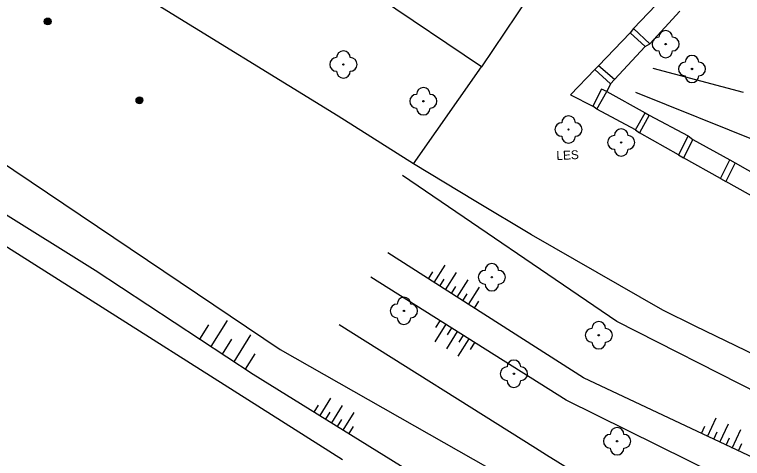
# Model space of a CAD drawing. Extents: x -539515 to -538098, y -1182060 to -1180157.
# Drawn here: x -538510.9 to -538457.6, y -1181768.2 to -1181735.7 of the extents above; entities that cross this region are included whole.
import ezdxf

# ---------------------------------------------------------------- set-up
doc = ezdxf.new("R2010")
doc.units = 0
for name, color, linetype in [('Vrstva 1', 7, 'Continuous'), ('Vrstva 13', 7, 'Continuous'), ('Vrstva 21', 7, 'Continuous'), ('Vrstva 22', 7, 'Continuous'), ('Vrstva 25', 7, 'Continuous'), ('Vrstva 27', 7, 'Continuous'), ('Vrstva 29', 7, 'Continuous'), ('Vrstva 40', 7, 'Continuous'), ('Vrstva 68', 7, 'Continuous'), ('Vrstva 88', 7, 'Continuous')]:
    doc.layers.add(name, color=color, linetype=linetype)

msp = doc.modelspace()

# ---------------------------------------------------------------- linework, layer by layer
at = {"layer": 'Vrstva 1'}
for p, q in [((-538476.685, -1181739.538), (-538490.817, -1181729.986)), ((-538471.65, -1181732.06), (-538476.685, -1181739.538))]:
    msp.add_line(p, q, dxfattribs=at)
at = {"layer": 'Vrstva 13'}
for p, q in [((-538465.54, -1181736.72), (-538465.78, -1181737.04)), ((-538465.78, -1181737.04), (-538464.69, -1181738.04)), ((-538464.33, -1181737.84), (-538465.54, -1181736.72)), ((-538464.69, -1181738.04), (-538464.33, -1181737.84)), ((-538466.92, -1181740.45), (-538468.11, -1181739.46)), ((-538464.13, -1181739.64), (-538457.51, -1181741.38)), ((-538467.23, -1181740.78), (-538466.92, -1181740.45)), ((-538468.22, -1181742.63), (-538467.48, -1181741.35)), ((-538465.39, -1181741.38), (-538456.26, -1181745.06)), ((-538468.22, -1181742.63), (-538468.52, -1181742.4)), ((-538465.397, -1181744.143), (-538464.68, -1181742.9)), ((-538464.68, -1181742.9), (-538464.38, -1181743.06)), ((-538464.38, -1181743.06), (-538465.1, -1181744.37)), ((-538465.397, -1181744.143), (-538465.1, -1181744.37)), ((-538461.54, -1181744.58), (-538462.235, -1181745.981)), ((-538461.54, -1181744.58), (-538461.2, -1181744.85)), ((-538461.2, -1181744.85), (-538461.865, -1181746.189)), ((-538462.235, -1181745.981), (-538461.865, -1181746.189)), ((-538459.161, -1181747.71), (-538458.47, -1181746.33)), ((-538458.09, -1181746.56), (-538458.77, -1181747.93)), ((-538458.47, -1181746.33), (-538458.09, -1181746.56)), ((-538459.161, -1181747.71), (-538458.77, -1181747.93))]:
    msp.add_line(p, q, dxfattribs=at)
for points in [[(-538468.11, -1181739.46), (-538468.37, -1181739.73), (-538467.23, -1181740.78)], [(-538467.48, -1181741.35), (-538467.89, -1181741.16), (-538468.52, -1181742.4)]]:
    msp.add_lwpolyline(points, dxfattribs=at)
at = {"layer": 'Vrstva 21'}
msp.add_line((-538481.67, -1181746.64), (-538476.685, -1181739.538), dxfattribs=at)
at = {"layer": 'Vrstva 22'}
for centre in [(-538463.18, -1181737.87), (-538486.8, -1181739.36), (-538461.25, -1181739.69), (-538480.94, -1181742.05), (-538470.3, -1181744.12), (-538466.44, -1181745.07), (-538475.92, -1181754.94), (-538482.36, -1181757.4), (-538468.08, -1181759.19), (-538474.3, -1181762), (-538466.74, -1181766.95)]:
    msp.add_circle(centre, 0.05, dxfattribs=at)
for centre, start, end in [((-538463.18, -1181737.37), 0, 180), ((-538463.68, -1181737.87), 90, 270), ((-538462.68, -1181737.87), 270, 90), ((-538486.8, -1181738.86), 0, 180), ((-538463.18, -1181738.37), 180, 0), ((-538461.25, -1181739.19), 0, 180), ((-538487.3, -1181739.36), 90, 270), ((-538486.3, -1181739.36), 270, 90), ((-538461.75, -1181739.69), 90, 270), ((-538460.75, -1181739.69), 270, 90), ((-538486.8, -1181739.86), 180, 0), ((-538461.25, -1181740.19), 180, 0), ((-538480.94, -1181741.55), 0, 180), ((-538481.44, -1181742.05), 90, 270), ((-538480.44, -1181742.05), 270, 90), ((-538480.94, -1181742.55), 180, 0), ((-538470.3, -1181743.62), 0, 180), ((-538470.8, -1181744.12), 90, 270), ((-538469.8, -1181744.12), 270, 90), ((-538466.94, -1181745.07), 90, 270), ((-538466.44, -1181744.57), 0, 180), ((-538465.94, -1181745.07), 270, 90), ((-538470.3, -1181744.62), 180, 0), ((-538466.44, -1181745.57), 180, 0), ((-538475.92, -1181754.44), 0, 180), ((-538476.42, -1181754.94), 90, 270), ((-538475.42, -1181754.94), 270, 90), ((-538475.92, -1181755.44), 180, 0), ((-538482.36, -1181756.9), 0, 180), ((-538482.86, -1181757.4), 90, 270), ((-538481.86, -1181757.4), 270, 90), ((-538482.36, -1181757.9), 180, 0), ((-538468.08, -1181758.69), 0, 180), ((-538468.58, -1181759.19), 90, 270), ((-538467.58, -1181759.19), 270, 90), ((-538468.08, -1181759.69), 180, 0), ((-538474.3, -1181761.5), 0, 180), ((-538474.8, -1181762), 90, 270), ((-538473.8, -1181762), 270, 90), ((-538474.3, -1181762.5), 180, 0), ((-538467.24, -1181766.95), 90, 270), ((-538466.74, -1181766.45), 0, 180), ((-538466.24, -1181766.95), 270, 90), ((-538466.74, -1181767.45), 180, 0)]:
    msp.add_arc(centre, 0.5, start, end, dxfattribs=at)
at = {"layer": 'Vrstva 25'}
for centre, radius in [((-538508.475, -1181736.21), 0.25), ((-538508.475, -1181736.21), 0.2), ((-538508.475, -1181736.21), 0.15), ((-538508.475, -1181736.21), 0.1), ((-538508.475, -1181736.21), 0.05), ((-538501.751, -1181741.979), 0.25), ((-538501.751, -1181741.979), 0.2), ((-538501.751, -1181741.979), 0.15), ((-538501.751, -1181741.979), 0.1), ((-538501.751, -1181741.979), 0.05)]:
    msp.add_circle(centre, radius, dxfattribs=at)
at = {"layer": 'Vrstva 27'}
for p, q in [((-538480.15, -1181755.325), (-538479.343, -1181754.06)), ((-538480.571, -1181755.055), (-538480.249, -1181754.55)), ((-538479.307, -1181755.863), (-538478.5, -1181754.598)), ((-538479.729, -1181755.594), (-538479.406, -1181755.088)), ((-538478.464, -1181756.401), (-538477.657, -1181755.137)), ((-538478.886, -1181756.132), (-538478.563, -1181755.626)), ((-538477.622, -1181756.939), (-538476.814, -1181755.675)), ((-538478.043, -1181756.67), (-538477.72, -1181756.164)), ((-538477.2, -1181757.208), (-538476.877, -1181756.702)), ((-538497.322, -1181759.469), (-538496.67, -1181758.423)), ((-538496.487, -1181760.019), (-538495.293, -1181758.104)), ((-538479.298, -1181758.386), (-538480.096, -1181759.656)), ((-538479.721, -1181758.12), (-538480.04, -1181758.628)), ((-538478.451, -1181758.918), (-538479.249, -1181760.188)), ((-538478.874, -1181758.652), (-538479.193, -1181759.16)), ((-538495.651, -1181760.57), (-538494.973, -1181759.481)), ((-538494.816, -1181761.12), (-538493.595, -1181759.162)), ((-538477.604, -1181759.45), (-538478.402, -1181760.72)), ((-538478.028, -1181759.184), (-538478.347, -1181759.692)), ((-538477.181, -1181759.716), (-538477.5, -1181760.224)), ((-538493.981, -1181761.67), (-538493.276, -1181760.539)), ((-538488.508, -1181765.073), (-538487.72, -1181763.797)), ((-538488.933, -1181764.81), (-538488.618, -1181764.3)), ((-538487.657, -1181765.599), (-538486.869, -1181764.322)), ((-538488.083, -1181765.336), (-538487.767, -1181764.825)), ((-538486.806, -1181766.124), (-538486.018, -1181764.848)), ((-538487.232, -1181765.861), (-538486.917, -1181765.351)), ((-538460.111, -1181766.591), (-538459.473, -1181765.234)), ((-538486.381, -1181766.387), (-538486.066, -1181765.876)), ((-538460.564, -1181766.378), (-538460.308, -1181765.835)), ((-538459.206, -1181767.017), (-538458.568, -1181765.66)), ((-538459.659, -1181766.804), (-538459.403, -1181766.261)), ((-538458.301, -1181767.443), (-538457.663, -1181766.085)), ((-538458.754, -1181767.23), (-538458.498, -1181766.687)), ((-538457.849, -1181767.656), (-538457.594, -1181767.113))]:
    msp.add_line(p, q, dxfattribs=at)
at = {"layer": 'Vrstva 29'}
for p, q in [((-538515.051, -1181744.345), (-538491.43, -1181760.23)), ((-538516.86, -1181747.048), (-538505, -1181754.41)), ((-538466.75, -1181758.19), (-538482.46, -1181747.49)), ((-538469.21, -1181762.31), (-538483.54, -1181753.16)), ((-538505, -1181754.41), (-538493.42, -1181762.04)), ((-538470.46, -1181763.94), (-538484.78, -1181754.94)), ((-538487.12, -1181758.41), (-538472.72, -1181767.42)), ((-538449.95, -1181766.71), (-538466.75, -1181758.19)), ((-538491.43, -1181760.23), (-538467.03, -1181774.07)), ((-538493.42, -1181762.04), (-538471.04, -1181775.86)), ((-538451.06, -1181770.85), (-538469.21, -1181762.31)), ((-538452.07, -1181773.01), (-538470.46, -1181763.94))]:
    msp.add_line(p, q, dxfattribs=at)
msp.add_lwpolyline([(-538472.72, -1181767.42), (-538471.902, -1181767.944), (-538471.079, -1181768.462), (-538470.253, -1181768.972), (-538469.422, -1181769.476), (-538468.587, -1181769.973), (-538467.748, -1181770.463), (-538466.905, -1181770.946), (-538466.058, -1181771.422), (-538465.207, -1181771.892), (-538464.352, -1181772.354)], dxfattribs=at)
at = {"layer": 'Vrstva 68'}
for p, q in [((-538487.19, -1181743.15), (-538509.48, -1181729.42)), ((-538486.86, -1181768.3), (-538526.69, -1181743.11)), ((-538481.67, -1181746.64), (-538487.19, -1181743.15)), ((-538463.39, -1181757.35), (-538473.02, -1181751.84)), ((-538461.01, -1181758.53), (-538463.39, -1181757.35))]:
    msp.add_line(p, q, dxfattribs=at)
for points in [[(-538473.02, -1181751.84), (-538477.1, -1181749.39), (-538481.67, -1181746.64)], [(-538448.94, -1181764.43), (-538451.27, -1181763.24), (-538461.01, -1181758.53)]]:
    msp.add_lwpolyline(points, dxfattribs=at)
at = {"layer": 'Vrstva 88'}
for p, q in [((-538463.25, -1181734.32), (-538465.54, -1181736.72)), ((-538462.13, -1181735.45), (-538464.33, -1181737.84)), ((-538465.78, -1181737.04), (-538468.11, -1181739.46)), ((-538464.69, -1181738.04), (-538466.92, -1181740.45)), ((-538467.23, -1181740.78), (-538467.48, -1181741.35)), ((-538467.48, -1181741.35), (-538464.68, -1181742.9)), ((-538465.397, -1181744.143), (-538468.22, -1181742.63)), ((-538464.38, -1181743.06), (-538461.54, -1181744.58)), ((-538462.235, -1181745.981), (-538465.1, -1181744.37)), ((-538461.2, -1181744.85), (-538458.47, -1181746.33)), ((-538459.161, -1181747.71), (-538461.865, -1181746.189)), ((-538458.09, -1181746.56), (-538455.32, -1181748.12)), ((-538456.03, -1181749.46), (-538458.77, -1181747.93))]:
    msp.add_line(p, q, dxfattribs=at)
msp.add_lwpolyline([(-538468.37, -1181739.73), (-538470.161, -1181741.59), (-538468.52, -1181742.4)], dxfattribs=at)

# ---------------------------------------------------------------- texts
at = {"layer": 'Vrstva 40'}
msp.add_text('LES', height=0.65, rotation=2.8766, dxfattribs=at).set_placement((-538471.174, -1181746.361))

doc.saveas('drawing.dxf')
